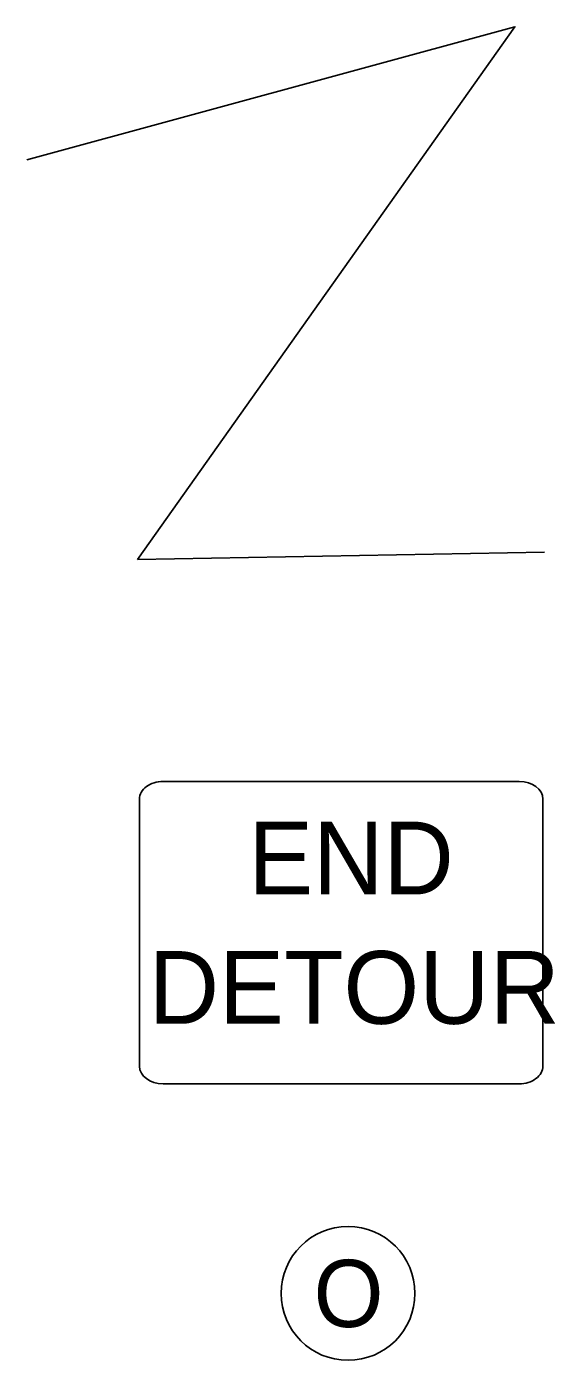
# Model space of a CAD drawing. Extents: x 2157572 to 5059327, y 715220 to 1674494.
# Drawn here: x 2166780 to 2167162, y 729307 to 730272 of the extents above; entities that cross this region are included whole.
import ezdxf

# ---------------------------------------------------------------- set-up
doc = ezdxf.new("R2010")
doc.units = 0
for name, color, linetype in [('Exist Cultural Church Label', 7, 'Continuous'), ('Exist Hydrographic Creek Double Shore Label', 7, 'Continuous'), ('Level 51', 7, 'Continuous'), ('Map Preparation County Base Legend Highway Garage or Maintenance Office', 7, 'Continuous')]:
    doc.layers.add(name, color=color, linetype=linetype)

msp = doc.modelspace()

# ---------------------------------------------------------------- linework, layer by layer
at = {"layer": 'Exist Cultural Church Label'}
msp.add_circle((2167012.28, 729355.28), 48.43, dxfattribs=at)
at = {"layer": 'Exist Hydrographic Creek Double Shore Label'}
msp.add_line((2166860.1, 729886.56), (2167154.45, 729891.92), dxfattribs=at)
msp.add_lwpolyline([(2166779.82, 730175.76), (2167133.04, 730272.16), (2166860.1, 729886.56)], dxfattribs=at)
at = {"layer": 'Level 51'}
for points in [[(2166878.44, 729725.83), (2167136.19, 729725.83)], [(2166861.42, 729519.75), (2166861.42, 729713.07)], [(2167153.21, 729713.06), (2167153.21, 729519.76)], [(2167136.19, 729506.98), (2166878.44, 729506.98)]]:
    msp.add_lwpolyline(points, dxfattribs=at)
for centre, major_axis, start_param, end_param in [((2166878.44, 729713.07), (-17.02, 0), 4.712162, 6.283185), ((2167136.19, 729713.07), (17.02, 0), 0, 1.570796), ((2166878.44, 729519.75), (-17.02, 0), 0, 1.570796), ((2167136.19, 729519.75), (-17.02, 0), 1.570796, 3.141593)]:
    msp.add_ellipse(centre, major_axis=major_axis, ratio=0.75, start_param=start_param, end_param=end_param, dxfattribs=at)
at = {"layer": 'Map Preparation County Base Legend Highway Garage or Maintenance Office'}
msp.add_circle((2167012.28, 729355.28), 48.43, dxfattribs=at)

# ---------------------------------------------------------------- texts
at = {"layer": 'Exist Cultural Church Label'}
msp.add_text('O', height=48.63, dxfattribs=at).set_placement((2166987.37, 729330.96))
at = {"layer": 'Level 51'}
for s, p in [('END', (2166940.08, 729644.09)), ('DETOUR', (2166868.12, 729550.41))]:
    msp.add_text(s, height=52.669, dxfattribs=at).set_placement(p)

doc.saveas('drawing.dxf')
